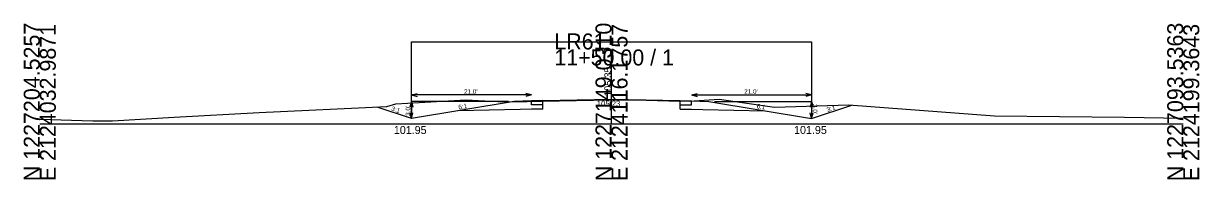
# Model space of a CAD drawing. Extents: x 2126751 to 2128979, y 1225108 to 1234639.
# Drawn here: x 2127773.8 to 2127979.4, y 1226607.5 to 1226634.8 of the extents above; entities that cross this region are included whole.
import ezdxf

# ---------------------------------------------------------------- set-up
doc = ezdxf.new("R2010")
doc.units = 0
for name, color, linetype in [('XS_CELL', 7, 'Continuous'), ('XS_M_DITCH', 7, 'Continuous'), ('XS_P_FINISHED_GRADE', 7, 'Continuous'), ('XS_P_FINISHED_GRADE_ELEV_TX', 7, 'Continuous'), ('XS_P_SUBGRADE_GRANULAR', 7, 'Continuous'), ('XS_P_SUBGRADE_LEVELING', 7, 'Continuous'), ('XS_P_SUBGRADE_PAVEMENT', 7, 'Continuous'), ('XS_P_TX_CLEARZONE', 7, 'Continuous'), ('XS_P_TX_DCH', 7, 'Continuous'), ('XS_P_TX_FS_BS', 7, 'Continuous'), ('XS_X_GROUND', 7, 'Continuous'), ('XS_X_GROUND_TX', 7, 'Continuous')]:
    doc.layers.add(name, color=color, linetype=linetype)

msp = doc.modelspace()

# ---------------------------------------------------------------- linework, layer by layer
at = {"layer": 'XS_CELL'}
for p, q in [((2127876.61, 1226617.21), (2127876.61, 1226630.23)), ((2127776.61, 1226617.21), (2127876.61, 1226617.21)), ((2127876.61, 1226617.21), (2127976.61, 1226617.21))]:
    msp.add_line(p, q, dxfattribs=at)
at = {"layer": 'XS_M_DITCH'}
for p, q in [((2127841.61, 1226618.16), (2127841.61, 1226631.56)), ((2127841.61, 1226631.56), (2127911.61, 1226631.56)), ((2127911.61, 1226631.56), (2127911.61, 1226618.16))]:
    msp.add_line(p, q, dxfattribs=at)
at = {"layer": 'XS_P_FINISHED_GRADE'}
for p, q in [((2127859.61, 1226621.16), (2127841.61, 1226618.16)), ((2127862.61, 1226621.28), (2127859.61, 1226621.16)), ((2127864.61, 1226621.32), (2127862.61, 1226621.28)), ((2127864.61, 1226621.32), (2127876.61, 1226621.56)), ((2127876.61, 1226621.56), (2127888.61, 1226621.32)), ((2127888.61, 1226621.32), (2127890.61, 1226621.28)), ((2127890.61, 1226621.28), (2127893.61, 1226621.16)), ((2127893.61, 1226621.16), (2127911.61, 1226618.16)), ((2127841.61, 1226618.16), (2127835.61, 1226620.16)), ((2127911.61, 1226618.16), (2127918.63, 1226620.5))]:
    msp.add_line(p, q, dxfattribs=at)
at = {"layer": 'XS_P_SUBGRADE_GRANULAR'}
for p, q in [((2127864.61, 1226619.82), (2127864.61, 1226620.57)), ((2127888.61, 1226619.82), (2127888.61, 1226620.57)), ((2127860.61, 1226619.74), (2127849.79, 1226619.52)), ((2127862.61, 1226619.78), (2127860.61, 1226619.74)), ((2127864.61, 1226619.82), (2127862.61, 1226619.78)), ((2127888.61, 1226619.82), (2127890.61, 1226619.78)), ((2127890.61, 1226619.78), (2127892.61, 1226619.74)), ((2127892.61, 1226619.74), (2127903.43, 1226619.52))]:
    msp.add_line(p, q, dxfattribs=at)
at = {"layer": 'XS_P_SUBGRADE_LEVELING'}
for p, q in [((2127864.61, 1226621.32), (2127864.61, 1226621.19)), ((2127864.61, 1226621.19), (2127867.43, 1226621.25)), ((2127867.43, 1226621.25), (2127876.43, 1226621.44)), ((2127876.43, 1226621.44), (2127882.7, 1226621.34)), ((2127882.7, 1226621.34), (2127888.61, 1226621.21)), ((2127888.61, 1226621.32), (2127888.61, 1226621.21))]:
    msp.add_line(p, q, dxfattribs=at)
at = {"layer": 'XS_P_SUBGRADE_PAVEMENT'}
for p, q in [((2127862.61, 1226620.53), (2127862.61, 1226621.28)), ((2127864.61, 1226620.57), (2127862.61, 1226620.53)), ((2127864.61, 1226620.57), (2127864.61, 1226621.19)), ((2127888.61, 1226620.57), (2127888.61, 1226621.21)), ((2127888.61, 1226620.57), (2127890.61, 1226620.53)), ((2127890.61, 1226620.53), (2127890.61, 1226621.28))]:
    msp.add_line(p, q, dxfattribs=at)
at = {"layer": 'XS_P_TX_CLEARZONE'}
for p, q in [((2127841.61, 1226621.16), (2127841.36, 1226620.16)), ((2127841.61, 1226622.28), (2127842.61, 1226622.53)), ((2127841.61, 1226622.28), (2127842.61, 1226622.03)), ((2127862.61, 1226622.28), (2127841.61, 1226622.28)), ((2127841.61, 1226621.16), (2127841.86, 1226620.16)), ((2127841.61, 1226621.16), (2127841.61, 1226618.16)), ((2127858.61, 1226621.16), (2127841.61, 1226621.16)), ((2127862.61, 1226622.28), (2127861.61, 1226622.53)), ((2127862.61, 1226622.28), (2127861.61, 1226622.03)), ((2127890.61, 1226622.28), (2127891.61, 1226622.53)), ((2127890.61, 1226622.28), (2127891.61, 1226622.03)), ((2127890.61, 1226622.28), (2127911.61, 1226622.28)), ((2127894.61, 1226621.16), (2127911.61, 1226621.16)), ((2127911.61, 1226622.28), (2127910.61, 1226622.53)), ((2127911.61, 1226622.28), (2127910.61, 1226622.03)), ((2127911.61, 1226621.16), (2127911.36, 1226620.16)), ((2127911.61, 1226621.16), (2127911.61, 1226618.16)), ((2127911.61, 1226621.16), (2127911.86, 1226620.16)), ((2127841.61, 1226618.16), (2127841.36, 1226619.16)), ((2127841.61, 1226618.16), (2127841.86, 1226619.16)), ((2127911.61, 1226618.16), (2127911.36, 1226619.16)), ((2127911.61, 1226618.16), (2127911.86, 1226619.16))]:
    msp.add_line(p, q, dxfattribs=at)
at = {"layer": 'XS_X_GROUND'}
for p, q in [((2127837.29, 1226620.24), (2127838.88, 1226620.74)), ((2127838.88, 1226620.74), (2127851.15, 1226621.43)), ((2127851.15, 1226621.43), (2127857.83, 1226621.07)), ((2127857.83, 1226621.07), (2127861.85, 1226621.14)), ((2127861.85, 1226621.14), (2127867.43, 1226621.25)), ((2127867.43, 1226621.25), (2127876.43, 1226621.44)), ((2127876.43, 1226621.44), (2127882.7, 1226621.34)), ((2127882.7, 1226621.34), (2127890.22, 1226621.18)), ((2127890.22, 1226621.18), (2127895.46, 1226621.55)), ((2127895.46, 1226621.55), (2127905.12, 1226620.14)), ((2127800.1, 1226618.38), (2127814.96, 1226619.24)), ((2127814.96, 1226619.24), (2127837.29, 1226620.24)), ((2127905.12, 1226620.14), (2127918.12, 1226620.54)), ((2127918.12, 1226620.54), (2127943.62, 1226618.64)), ((2127943.62, 1226618.64), (2127966.32, 1226618.37)), ((2127776.61, 1226618.06), (2127785.91, 1226617.74)), ((2127785.91, 1226617.74), (2127788.48, 1226617.74)), ((2127788.48, 1226617.74), (2127789.35, 1226617.78)), ((2127789.35, 1226617.78), (2127800.1, 1226618.38)), ((2127966.32, 1226618.37), (2127976.61, 1226618.21))]:
    msp.add_line(p, q, dxfattribs=at)

# ---------------------------------------------------------------- texts
at = {"layer": 'XS_CELL'}
for s, p in [('N 1227204.5257', (2127776.61, 1226607.21)), ('E 2124032.9871', (2127779.41, 1226607.21)), ('N 1227149.0310', (2127876.61, 1226607.21)), ('E 2124116.1757', (2127879.41, 1226607.21)), ('N 1227093.5363', (2127976.61, 1226607.21)), ('E 2124199.3643', (2127979.41, 1226607.21))]:
    msp.add_text(s, height=2.8, rotation=90, dxfattribs=at).set_placement(p)
for s, p in [('LR61', (2127866.61, 1226630.23)), ('11+50.00 / 1', (2127866.61, 1226627.43))]:
    msp.add_text(s, height=2.8, dxfattribs=at).set_placement(p)
at = {"layer": 'XS_P_FINISHED_GRADE_ELEV_TX'}
msp.add_text(' 105.35', height=1.25, rotation=90, dxfattribs=at).set_placement((2127876.61, 1226621.56))
at = {"layer": 'XS_P_TX_CLEARZONE'}
for p in [(2127850.82, 1226622.48), (2127899.82, 1226622.48)]:
    msp.add_text("21.0'", height=0.8, dxfattribs=at).set_placement(p)
for rotation, p in [(270, (2127911.81, 1226620.69)), (90, (2127841.41, 1226618.63))]:
    msp.add_text("3.0'", height=0.8, rotation=rotation, dxfattribs=at).set_placement(p)
at = {"layer": 'XS_P_TX_DCH'}
for p in [(2127838.54, 1226615.46), (2127908.54, 1226615.46)]:
    msp.add_text('101.95', height=1.4, dxfattribs=at).set_placement(p)
at = {"layer": 'XS_P_TX_FS_BS'}
for s, rotation, p in [('6:1', 9.4623, (2127849.89, 1226619.74)), ('6:1', 350.5377, (2127901.95, 1226619.97)), ('3:1', 341.5651, (2127838.02, 1226619.57)), ('3:1', 18.4349, (2127914.41, 1226619.3))]:
    msp.add_text(s, height=0.8, rotation=rotation, dxfattribs=at).set_placement(p)
at = {"layer": 'XS_X_GROUND_TX'}
msp.add_text('105.23', height=1, dxfattribs=at).set_placement((2127874.05, 1226620.27))

doc.saveas('drawing.dxf')
